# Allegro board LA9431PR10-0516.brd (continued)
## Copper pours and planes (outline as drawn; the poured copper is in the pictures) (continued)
INT_SPK_R- on TOP (solid shape): 268.87,34.04 269.1,34.04 269.41,33.73 270.18,33.73 270.23,33.68 270.23,33.48 270.19,33.44 268.85,33.44 268.29,34 268.29,34.15 268.35,34.21 268.69,34.21
INT_SPK_R- on TOP (solid shape): 273.62,22.83 273.62,22.52 273.37,22.26 273.37,21.54 273.81,21.09 273.81,20.18 273.76,20.13 272.4,20.13 272.1,20.43 272.1,22.78 272.22,22.91 273.55,22.91
INT_SPK_R- on IN1 (solid shape): 273.65,23.37 273.65,22.57 273.49,22.41 272.76,22.41 272.2,22.97 272.2,23.44 272.63,23.88 273.14,23.88
INT_SPK_R- on IN1 (solid shape): 268.83,34.04 269.32,34.04 270.12,33.24 270.12,32.93 269.63,32.45 269.44,32.45 269.01,32.88 269.01,33.22 269.01,33.23 269.01,33.32 268.26,34.06 268.26,34.16 268.36,34.26 268.61,34.26
INT_SPKR_L+ on TOP (solid shape): 281.31,19.51 281.31,15.67 280.44,14.81 279.32,14.81 279.15,14.63 279.15,13.31 279.25,13.21 283.18,13.21 283.32,13.07 283.32,12.5 283.24,12.41 281.7,12.41 281.62,12.48 278.26,12.48 277.84,12.9 277.84,15.75 279.22,17.13 279.22,19.49 279.5,19.77 281.04,19.77
INT_SPKR_L- on TOP (solid shape): 278.84,19.39 278.84,17.23 277.89,16.28 277.89,16.27 277.55,15.93 277.55,12.78 278.05,12.27 281.44,12.27 281.56,12.15 283.17,12.15 283.31,12.01 283.31,11.73 283.19,11.61 277.19,11.61 276.05,12.75 276.05,16.8 276.8,17.55 276.8,19.64 276.92,19.76 278.48,19.76
INT_SPKR_R+ on TOP (solid shape): 276.51,19.63 276.51,17.64 275.76,16.88 275.76,12.69 277.09,11.35 283.21,11.35 283.32,11.24 283.32,10.91 283.18,10.77 281.56,10.77 281.46,10.67 276,10.67 273.95,12.71 273.95,17.25 274.36,17.65 274.36,19.54 274.58,19.76 276.38,19.76
INT_SPKR_R- on TOP (solid shape): 274.08,19.57 274.08,17.75 273.57,17.25 273.57,12.66 275.82,10.41 281.61,10.41 281.71,10.52 283.2,10.52 283.3,10.41 283.3,10.03 283.01,9.74 274.46,9.74 271.93,12.27 271.93,19.64 272.09,19.8 273.85,19.8
LG_3V on TOP (solid shape): 198.22,58.83 198.22,58.34 197.76,57.89 196.47,57.89 196.27,58.09 196.27,58.58 196.63,58.95 198.09,58.95
LG_3V on TOP (solid shape): 198.32,52.43 198.32,51.26 197.76,50.7 197.76,50.41 197.71,50.35 197.57,50.35 197.51,50.41 197.51,51.16 197.7,51.34 197.7,52.41 197.79,52.5 198.25,52.5
LG_3V on IN4 (solid shape): 197.59,58.42 197.59,57.25 197.16,56.82 196.85,56.82 196.32,57.35 196.32,58.7 196.44,58.83 197.18,58.83
LG_3V on IN4 (solid shape): 198.4,53.64 198.4,51.56 198.17,51.33 197.46,51.33 197.21,51.59 197.21,53.49 197.59,53.87 198.17,53.87
LG_5V on TOP (solid shape): 193.98,61 193.98,60.17 193.85,60.05 193.03,60.05 192.84,60.24 192.84,61 192.96,61.12 193.85,61.12
LG_5V on TOP (solid shape): 196.14,51.13 196.14,50.4 196.09,50.35 195.99,50.35 195.94,50.4 195.94,50.52 195.89,50.57 195.38,50.57 194.77,51.18 194.77,51.46 194.93,51.62 195.64,51.62
LG_5V on IN4 (solid shape): 193.98,61.06 193.98,59.79 193.83,59.64 192.99,59.64 192.86,59.77 192.86,61.01 193.04,61.19 193.85,61.19
LG_5V on IN4 (solid shape): 195.31,53.99 195.31,52.26 195.78,51.79 195.78,50.75 195.63,50.6 195.38,50.6 194.32,51.65 194.32,53.96 194.5,54.14 195.16,54.14
LG_+V1.05SP on TOP (solid shape): 233.54,78.24 233.54,77.33 233.48,77.27 231.7,77.27 231.64,77.33 231.64,77.77 231.89,78.03 232.33,78.03 232.61,78.31 233.48,78.31
LG_+V1.05SP on TOP (solid shape): 236.33,76.11 236.33,75.73 236.12,75.51 236.12,75.01 236.02,74.9 235.38,74.9 235.28,75.01 235.28,75.72 235.79,76.24 236.21,76.24
LG_+V1.05SP on IN1 (solid shape): 236.33,77.02 236.33,75.96 235.74,75.36 235.26,75.36 235.13,75.49 235.13,77.09 234.96,77.25 233.16,77.25 232.49,77.93 232.49,78.27 232.82,78.6 234.76,78.6
NB_PSID on BOTTOM (solid shape): 92.62,93.08 92.62,92.66 92.36,92.4 92.28,92.34 92.22,92.26 92.02,92.06 88.95,92.06 88.84,92.18 88.84,92.43 88.88,92.47 88.88,92.49 89.67,93.29 92.41,93.29
PBATT+_C on TOP (solid shape): 172.83,9.88 172.83,5.12 171.88,4.17 171.88,2.01 171.69,1.82 167.82,1.82 167.44,2.2 167.44,5.44 168.33,6.32 168.33,9.88 168.52,10.07 172.64,10.07
REGCTL_PNP10 on TOP (solid shape): 261.06,73.06 261.06,71.93 260.97,71.84 259.52,71.84 259.49,71.86 259.49,72.93 259.78,73.21 260.91,73.21
REGCTL_PNP10 on IN1 (solid shape): outline of 145 points within 256.53,72.17 260.97,78.71
RING2 on TOP (solid shape): 277.37,39.47 277.88,39.47 278,39.34 278,38.94 277.81,38.75 275.64,38.75 274.73,37.83 274.73,36.98 274.68,36.93 274.5,36.93 274.43,36.99 274.43,38.02 275.94,39.53 276.55,39.53 276.79,39.78 277.06,39.78
RING2 on BOTTOM (solid shape): 274.66,47.65 274.66,46.63 274.49,46.46 273.84,46.46 273.47,46.82 273.47,47.6 273.57,47.7 274.61,47.7
RING2 on IN1 (solid shape): outline of 184 points within 272.96,38.73 278,47.75
RING2_L on BOTTOM (solid shape): 277.13,53.97 277.13,52.42 277.1,52.39 277.1,52.06 276.75,51.71 276.75,49.73 276.29,49.26 276.29,47.77 276,47.48 275.98,47.46 275.98,46.98 275.86,46.85 275.26,46.85 275.06,47.05 275.06,50.91 275.21,51.26 274.95,51.55 274.92,51.56 274.92,53.07 274.66,53.33 274.66,54.18 274.78,54.29 276.81,54.29
RING2_L on IN1 (solid shape): 275.92,54.11 275.92,52.37 275.5,51.96 272.87,51.96 272.69,52.13 272.69,53.81 273.13,54.24 275.79,54.24
RING2_L on IN1 (solid shape): 270.95,67.61 271.16,67.55 271.36,67.61 272.14,67.61 272.47,67.17 273,67 274.8,67 275.33,67.17 275.66,67.61 279.39,67.61 279.67,67.2 280.13,67 280.15,67 281.18,65.98 281.18,64.36 281.03,64.21 278.28,64.21 277.49,65.01 277.49,65.03 277.29,65.44 276.86,65.6 275.95,65.6 275.65,65.53 275.43,65.32 273.29,65.32 273.06,65.53 272.76,65.6 271.85,65.6 271.56,65.53 271.34,65.34 271.32,65.32 271.26,65.32 271.18,65.36 271.17,65.46 270.84,65.95 270.51,65.46 270.5,65.36 270.42,65.32 270,65.32 268.95,66.37 268.95,67.09 269.47,67.61
RUNPWROK on IN1 (solid shape): outline of 211 points within 74.16,71.41 78.98,76.75
S5_1.35V on TOP (solid shape): 119.91,11.1 119.91,8.86 119.79,8.74 119.28,8.74 118.97,9.04 118.97,9.64 118.32,10.29 116.96,10.29 116.92,10.33 116.92,10.52 116.96,10.56 118.58,10.56 119.23,11.2 119.81,11.2
SLEEVE on TOP (solid shape): 276.45,41.24 276.45,40.68 276.36,40.58 275.98,40.58 275.92,40.52 275.92,39.72 274.24,38.04 274.24,36.98 274.18,36.93 274,36.93 273.95,36.98 273.95,38.59 274.42,39.07 274.42,40.94 274.89,41.41 276.29,41.41
SLEEVE on TOP (solid shape): 271.77,51.24 271.77,50.57 271.97,50.37 272.35,50.37 272.85,49.87 272.85,48.81 272.78,48.74 271.98,48.74 270.7,50.02 270.7,51.03 271.03,51.36 271.65,51.36
SLEEVE on IN4 (solid shape): outline of 299 points within 271.28,38.68 276.02,50.43
SLEEVE_L on TOP (solid shape): 281.8,55.6 281.8,54.56 280.33,53.09 280.33,51.15 280.34,51.01 280.35,50.89 280.35,49.83 280.24,49.72 280.22,49.72 279.32,49.63 278.45,49.37 278.42,49.37 278.4,49.35 278.15,49.24 277.92,49.11 274.66,49.11 273.72,50.05 273.06,50.05 272.61,50.51 272.07,50.51 272.01,50.57 272.01,51.24 272.05,51.28 273.89,51.28 274.36,50.81 276.38,50.81 276.64,50.55 277.83,50.55 278.17,50.89 278.17,53.53 279.21,54.57 279.21,55.55 279.59,55.93 281.47,55.93
SNUB_1.35V on TOP (solid shape): 101.77,16.09 101.77,16.08 101.84,15.98 101.94,15.91 101.95,15.9 102.46,15.39 102.46,13.46 102.36,13.36 101.65,13.36 100.48,14.53 100.48,16.26 100.56,16.33 101.52,16.33
SW1 on TOP (solid shape): 192.39,61.25 192.39,58.14 192.2,57.95 191.19,57.95 190.3,57.06 187.76,57.06 187.57,57.25 187.57,61.25 187.82,61.51 192.14,61.51
SW1 on TOP (solid shape): 194.54,49.35 195.73,49.35 195.76,49.33 195.76,49.18 195.71,49.13 194.65,49.13 194.53,49.02 194.5,49.02 194.43,48.95 194.34,48.95 193.98,48.59 192.7,48.59 192.66,48.6 192.65,48.64 192.65,48.68 192.62,48.82 192.54,48.95 192.53,48.97 192.53,49.5 192.63,49.61 194.28,49.61
SW1 on BOTTOM (solid shape): 193.22,59.66 193.22,56.68 193.09,56.55 189.41,56.55 188.07,57.89 188.07,60.49 188.27,60.68 192.2,60.68
SW1 on IN4 (solid shape): 194.56,49.81 194.56,49.02 194.51,48.97 193.5,48.97 192.76,49.71 192.76,50.6 192.91,50.75 193.62,50.75
SW1 on IN4 (solid shape): 190.65,59.87 190.65,57.66 190.58,57.58 189.56,57.58 189.26,57.88 189.26,59.95 189.36,60.04 190.48,60.04
SW2 on TOP (solid shape): 202.95,61.16 202.95,56.77 202.79,56.62 201.18,56.62 201.1,56.69 201.1,58.1 200.81,58.39 198.93,58.39 198.74,58.58 198.74,60.93 199.28,61.47 202.64,61.47
SW2 on TOP (solid shape): 201.02,49.35 201.02,48.46 200.99,48.44 200.3,48.44 199.87,48.87 199.16,48.87 198.96,49.07 198.91,49.12 197.95,49.12 197.93,49.14 197.93,49.31 197.97,49.35 199.1,49.35 199.15,49.4 200.97,49.4
SW2 on BOTTOM (solid shape): 202.16,60.99 202.31,60.84 202.31,57.58 201.35,56.62 197.09,56.62 197.03,56.68 197.03,59.73 198.77,61.47 201.69,61.47
SW2 on IN1 (solid shape): 200.91,50.27 200.91,49.07 200.63,48.79 199.06,48.79 198.96,48.89 198.96,49.35 199.97,50.37 200.81,50.37
SW2 on IN1 (solid shape): 202.57,58.8 202.57,57.25 202.51,57.2 201.52,57.2 201.12,57.61 201.12,58.9 201.27,59.05 202.31,59.05
SW_1.35V on TOP (solid shape): 113.21,13.44 113.21,12.5 113.67,12.04 114.1,12.04 114.7,11.43 114.7,11.16 114.65,11.11 113.83,11.11 113.56,11.38 113.16,11.38 112.34,12.19 112.34,13.44 112.42,13.51 113.13,13.51
SW_1.35V on TOP (solid shape): 102.73,12.55 105.65,12.55 106.99,11.21 107.49,11.21 107.62,11.09 107.62,9.18 107.49,9.05 106.16,9.05 105.84,8.74 102.35,8.74 102.22,8.86 102.22,10.21 101.46,10.97 101.46,12.8 101.59,12.93 102.35,12.93
SW_1.35V on BOTTOM (solid shape): 107.85,13.54 107.85,9.25 107.34,8.74 102.44,8.74 102.26,8.91 102.26,11.53 104.8,14.07 107.32,14.07
SW_1.35V on IN4 (solid shape): 106.15,12.32 106.15,11.58 105.69,11.12 103.76,11.12 103.58,11.3 103.58,12.27 103.86,12.55 105.92,12.55
SW_1.35V on IN4 (solid shape): 113.28,12.12 114.43,12.12 114.48,12.06 114.48,11.51 114.38,11.4 111.68,11.4 111.51,11.58 111.51,12.45 111.63,12.57 112.83,12.57
SW_+V1.05SP on TOP (solid shape): 236.12,74.12 236.12,74.04 235.99,73.91 234.62,73.91 233.93,73.23 233.93,72.01 233.83,71.91 232.97,71.91 232.89,71.98 232.89,72.97 234.14,74.22 236.02,74.22
SW_+V1.05SP on TOP (solid shape): 229.67,79.48 229.67,77.88 229.79,77.75 231.11,77.75 231.24,77.62 231.24,74.6 230.91,74.27 229.87,74.27 229.87,74.27 229.58,74.27 229.44,74.12 229.44,73.46 229.31,73.33 227.51,73.33 227.38,73.46 227.38,77.01 228.77,78.4 228.77,79.54 228.83,79.6 229.54,79.6
SW_+V1.05SP on BOTTOM (solid shape): 230.56,77.7 230.68,77.7 230.88,77.49 230.88,72.83 230.82,72.77 228.18,72.77 227.29,73.66 227.29,77.48 227.51,77.7 230.56,77.7
SW_+V1.05SP on IN1 (solid shape): 228.91,77.49 228.91,74.24 228.57,73.9 227.64,73.9 227.37,74.17 227.37,77.49 227.48,77.61 228.79,77.61
SW_+V1.05SP on IN1 (solid shape): 234.49,74.12 234.49,73.76 232.84,72.11 232.26,72.11 232.11,72.26 232.11,72.85 233.55,74.29 234.32,74.29
UG_3V on TOP (solid shape): 199.39,51.28 199.39,50.47 198.81,49.89 198,49.89 197.94,49.95 197.94,50.1 198.03,50.2 198.4,50.2 198.68,50.47 198.68,51.26 198.81,51.38 199.29,51.38
UG_3V on TOP (solid shape): 200.95,57.58 200.95,56.74 200.16,55.96 199.28,55.96 199.16,56.08 199.16,56.34 199.28,56.46 199.53,56.46 199.68,56.46 199.69,56.47 199.79,56.47 200.11,56.79 200.11,56.97 200.11,56.97 200.3,57.16 200.3,57.54 200.46,57.71 200.82,57.71
UG_3V on IN1 (solid shape): 199.66,52.23 199.66,50.35 199.29,49.99 198.51,49.99 198.41,50.09 198.41,52.31 198.62,52.51 199.38,52.51
UG_3V on IN1 (solid shape): 200.66,56.49 200.66,55.07 200.38,54.79 199.18,54.79 199,54.97 199,56.49 199.1,56.59 200.56,56.59
UG_5V on TOP (solid shape): 187.38,59.47 187.38,57.25 187.25,57.12 187.06,57.12 186.74,57.44 186.74,59.47 186.8,59.54 187.31,59.54
UG_5V on TOP (solid shape): 195.25,50.27 195.61,50.27 195.73,50.14 195.73,49.95 195.7,49.91 194.65,49.91 193.73,50.84 193.73,51.22 193.85,51.35 194.17,51.35
UG_5V on IN1 (solid shape): 194.96,50.6 194.96,50.09 194.84,49.97 192.93,49.97 192.37,50.53 192.37,51.71 192.53,51.88 193.68,51.88
UG_5V on IN1 (solid shape): 187.69,59.54 187.69,58.9 188.33,58.27 188.33,57.63 188.07,57.38 187.57,57.38 186.87,58.08 186.87,59.41 187.12,59.66 187.57,59.66
UG_+V1.05SP on TOP (solid shape): 227.14,75.71 227.14,74.42 227.19,74.37 227.19,73.57 227,73.38 226.68,73.38 226.62,73.44 226.62,75.73 226.68,75.79 227.06,75.79
UG_+V1.05SP on TOP (solid shape): 236.12,73.68 236.12,73.51 236.04,73.43 235.31,73.43 234.57,72.69 234.19,72.69 234.09,72.8 234.09,73.08 234.75,73.74 236.07,73.74
UG_+V1.05SP on IN1 (solid shape): 235.19,73.57 235.19,72.3 234.57,71.68 234.19,71.68 234.09,71.78 234.09,73.02 234.82,73.76 235,73.76
UG_+V1.05SP on IN1 (solid shape): 227.13,75.67 227.13,74.44 227.18,74.39 227.18,73.84 226.93,73.58 226.55,73.58 226.36,73.77 226.36,75.53 226.56,75.73 227.07,75.73
USH_PWR_STATE# on TOP (solid shape): 191.08,8.23 191.08,6.65 190.91,6.48 190.91,5.54 190.86,5.49 190.63,5.49 190.59,5.52 190.59,6.67 189.6,7.66 189.6,8.36 190.96,8.36
N16994246 on TOP (solid shape): 54.13,14.59 54.13,12.56 54.08,12.51 53.09,12.51 52.48,13.12 51.99,13.12 51.74,13.37 51.74,13.82 51.87,13.94 52.45,13.94 53.26,14.76 53.96,14.76
N17156946 on TOP (solid shape): 52.35,41.45 52.35,40.79 52.5,40.64 53.54,40.64 53.65,40.54 53.65,37.52 53.57,37.44 53.16,37.44 52.32,38.28 51.51,38.28 51.41,38.38 51.41,39.6 51.71,39.9 51.71,40.66 51.61,40.77 51.61,41.48 51.69,41.55 52.25,41.55
N17156946 on BOTTOM (solid shape): 53.66,37.8 53.66,37.01 53.39,36.74 52.73,36.74 52.59,36.87 52.59,37.97 52.73,38.11 53.35,38.11
N17219423 on TOP (solid shape): 49.14,17.25 49.14,12.77 48.79,12.42 47.93,12.42 47.8,12.55 47.8,17.25 47.93,17.37 49.02,17.37
N17318583 on BOTTOM (solid shape): 155.68,15.26 155.68,13.94 155.6,13.87 155.04,13.87 154.69,13.51 154.69,11.3 153.77,10.39 152.6,10.39 152.48,10.52 152.48,11.33 153.92,12.78 153.92,13.74 153.64,14.02 151.84,14.02 151.46,13.64 150.34,13.64 150.09,13.89 150.09,14.99 150.5,15.39 155.55,15.39
N17321677 on TOP (solid shape): 128.07,9.42 128.07,9.25 127.69,8.86 127.69,7.72 127.88,7.53 127.88,5.88 128.19,5.56 129.34,5.56 129.59,5.31 129.59,5.12 129.53,5.05 127.88,5.05 127.58,5.35 127.58,5.36 127.57,5.36 127.43,5.5 126.86,5.5 126.73,5.63 125.4,5.63 125.03,6 125.03,6.21 125.12,6.48 124.99,6.73 124.97,6.75 124.97,6.77 124.97,8.2 125.12,8.36 125.7,8.36 125.86,8.51 125.86,8.97 126.44,9.55 127.94,9.55
N17663289 on TOP (solid shape): 69.52,12.29 69.52,5.5 69.14,5.12 65.39,5.12 64.5,4.23 64.5,3.28 64.38,3.15 63.49,3.15 63.42,3.21 63.42,9.44 65.14,11.15 65.14,13.75 65.33,13.94 67.87,13.94
N17663289 on TOP (solid shape): 52.83,12.45 52.83,11.84 52.78,11.79 52.55,11.79 52.25,11.48 52.25,10.11 52.2,10.06 52.2,9.17 52.15,9.12 51.99,9.12 51.92,9.19 51.92,10.36 51.74,10.54 51.74,12.47 51.84,12.57 52.71,12.57
N17663289 on BOTTOM (solid shape): 69.46,12.23 69.46,5.88 69.27,5.69 62.85,5.69 61.84,6.71 61.84,12.36 62.09,12.61 69.08,12.61
N17663289 on IN2 (solid shape): 52.25,12.78 52.25,10.57 52.07,10.39 51.08,10.39 50.93,10.54 50.93,12.78 51.16,13 52.02,13
N17663289 on IN2 (solid shape): 69.43,10.69 69.43,7.98 69.28,7.82 68.44,7.82 68.29,7.98 68.29,10.69 68.47,10.87 69.25,10.87
N19638084 on BOTTOM (solid shape): 100.03,98.4 100.06,98.38 100.08,98.35 100.08,97.7 100.08,97.67 100.2,97.55 101.02,97.55 101.05,97.57 101.05,98.08 101.06,98.1 101.21,98.1 101.24,98.07 101.24,97.57 101.25,97.56 102.83,97.56 103.05,97.34 103.05,96.18 103.09,96.13 103.59,96.13 103.63,96.09 103.63,95.98 103.62,95.97 103.1,95.97 103.07,95.93 103.07,95.59 103.04,95.56 102.86,95.56 102.81,95.6 102.49,95.6 102.41,95.61 102.34,95.6 100.66,95.6 99.91,94.85 99.91,92.56 99.78,92.44 97.3,92.44 97.21,92.52 97.2,92.54 97.2,92.56 97.2,95.52 97.99,96.31 98.93,97.25 98.93,98.29 99.04,98.4
N19641658 on TOP (solid shape): 41.71,7.47 42.18,7.47 42.39,7.26 42.4,7.25 42.41,7.23 42.41,6.71 42.66,6.45 43.18,6.45 43.2,6.45 43.21,6.44 43.42,6.22 43.42,6.04 43.26,5.88 42.34,5.88 41.52,6.71 41.51,6.71 41.48,6.73 41.48,6.87 40.68,6.87 40.64,6.88 40.63,6.92 40.63,7.59 40.69,7.65 41.52,7.65
N19643962 on TOP (solid shape): 43.42,4.93 43.42,4.48 43.04,4.1 43.04,3.53 42.66,3.15 41.58,3.15 41.52,3.21 41.52,4.46 42.11,5.05 43.29,5.05
N19721969 on BOTTOM (solid shape): 85.85,65.7 90.69,65.7 91.19,65.2 91.19,62.74 91.17,62.71 91.14,62.69 88.68,62.69 88.68,61.93 91.14,61.93 91.17,61.91 91.19,61.88 91.19,60.38 91.01,60.2 87.15,60.2 86.79,60.55 86.79,62.56 86.69,62.66 84.75,62.66 83.76,63.66 83.76,66.84 83.77,66.85 84.7,66.85
N19817114 on BOTTOM (solid shape): outline of 496 points within 177.06,7.04 192.66,15.44
N19817114 on IN4 (solid shape): outline of 291 points within 177.11,7.9 191.54,15.52
N19955529 on TOP (solid shape): 135.51,12.54 135.51,11.22 134.33,10.04 134.33,8.95 134.19,8.81 133.1,8.81 132.9,9.01 132.9,11.23 132.1,12.03 131.3,12.03 131.27,12.06 131.27,12.7 131.3,12.73 135.32,12.73
N19969338 on TOP (solid shape): 176.89,11.05 176.89,10.43 176.72,10.27 176.17,10.27 175.57,9.67 174.79,9.67 174.67,9.79 174.67,11.04 174.76,11.13 176.81,11.13
N20097876 on BOTTOM (solid shape): outline of 95 points within 197,6.53 200.46,10.07
N20124570 on TOP (solid shape): 94.12,89.93 94.12,88.09 93.75,87.72 93.75,87.2 93.69,87.13 93.07,87.13 93.04,87.16 93.04,87.81 93.47,88.24 93.47,89.9 93.57,90 94.04,90
N48708347 on TOP (solid shape): 111.94,13.28 111.94,11.45 111.84,11.35 111.05,11.35 110.85,11.56 110.85,13.33 110.95,13.44 111.79,13.44
N61501060 on BOTTOM (solid shape): 86.51,61.21 86.51,60.1 86.39,59.97 83.62,59.97 83.49,60.1 83.49,60.83 83.59,60.93 84.46,60.93 84.84,61.32 86.41,61.32
N66972030 on TOP (solid shape): 192,50.8 192,48.97 192,48.95 191.91,48.82 191.88,48.68 191.88,48.58 191.76,48.46 191.29,48.46 191.11,48.64 191.11,50.75 191.21,50.85 191.95,50.85
N66972333 on TOP (solid shape): 202.62,50.71 202.62,48.62 202.43,48.42 201.6,48.42 201.54,48.49 201.54,50.71 201.66,50.84 202.49,50.84
N66980103 on TOP (solid shape): 191.31,63.28 191.31,61.82 191.19,61.7 188.84,61.7 188.77,61.76 188.77,63.22 189.03,63.47 191.12,63.47
N66983215 on TOP (solid shape): 202.22,62.84 202.72,62.84 202.87,62.69 202.87,61.9 202.67,61.7 200.6,61.7 200.52,61.77 200.52,63.41 200.58,63.47 201.58,63.47
N66984844 on TOP (solid shape): 232.65,80.09 232.65,78.66 232.39,78.4 230.17,78.4 230.04,78.53 230.04,80.06 230.19,80.21 232.52,80.21
N78934544 on TOP (solid shape): 179.02,7.82 179.02,5.71 178.89,5.59 178.38,5.59 178.28,5.69 178.28,6.2 177.93,6.55 177.55,6.55 177.42,6.68 177.42,7.87 177.55,8 178.84,8
N78935279 on TOP (solid shape): 177.16,9.58 177.16,8.37 177.06,8.28 176.73,8.28 175.73,7.28 174.78,7.28 174.7,7.36 174.7,8.66 174.84,8.8 175.32,8.8 176.19,9.67 177.06,9.67
N78945927 on TOP (solid shape): 131.55,7.15 131.55,6.44 131.37,6.26 131.37,5.05 131.31,4.99 129.97,4.99 129.85,5.12 129.85,6.02 129.97,6.14 129.97,6.32 130.67,7.02 130.67,7.21 130.73,7.28 131.42,7.28
N78963697 on TOP (solid shape): 140.72,10.77 140.72,10.01 140.61,9.91 138.89,9.91 138.81,9.98 138.81,10.39 138.94,10.52 139.8,10.52 140.11,10.82 140.67,10.82
N79021833 on TOP (solid shape): 135.5,8.17 135.5,7.53 135.43,7.47 134.21,7.47 133.96,7.21 133.96,6.35 133.91,6.3 133.35,6.3 133.07,6.58 133.07,8.15 133.27,8.36 135.31,8.36
N79026826 on TOP (solid shape): 140.61,9.44 140.61,7.85 140.46,7.7 139.65,7.7 139.47,7.87 138.61,7.87 138.53,7.95 138.53,8.7 138.75,8.92 138.75,9.58 138.8,9.63 140.42,9.63
N79030038 on BOTTOM (solid shape): 205.99,4.23 206.29,4.23 206.29,4.22 206.88,4.22 207.11,3.99 207.11,3.09 206.98,2.96 204.62,2.96 203.97,3.61 203.97,4.8 204.04,4.86 205.36,4.86
N79030087 on BOTTOM (solid shape): 203.68,5.49 203.68,5.18 203.56,5.05 202.37,5.05 201.87,5.56 200.55,5.56 200.44,5.66 200.44,6.2 200.52,6.28 202.89,6.28
N79030091 on BOTTOM (solid shape): 199.24,6.26 200.04,6.26 200.2,6.1 200.2,4.63 200.07,4.5 199.53,4.5 199.39,4.64 199.39,5.34 199.12,5.6 197.72,5.6 197.31,6.02 197.31,6.53 197.61,6.83 198.67,6.83
N79030745 on BOTTOM (solid shape): 196.84,5.66 196.84,4.86 195.31,3.34 192.6,3.34 192.38,3.56 192.38,5.16 192.72,5.5 194.42,5.5 194.93,6.01 196.49,6.01
N79031357 on TOP (solid shape): 202.92,16.71 202.92,15.88 202.82,15.78 201.59,15.78 201.58,15.79 201.15,15.79 200.39,16.55 200.39,16.55 200.39,16.74 200.47,16.81 202.82,16.81
N79031406 on TOP (solid shape): 206.27,14.24 206.27,12.81 206.22,12.76 205.73,12.76 204.7,11.74 203.63,11.74 203.31,12.06 203.31,12.99 203.59,13.26 204.79,13.26 205.04,13.51 205.54,13.42 205.62,13.92 205.64,13.94 205.64,14.08 205.64,14.08 205.64,14.23 205.7,14.29 206.22,14.29
N79031414 on TOP (solid shape): 200.74,15 202.5,15 202.92,14.58 202.92,13.54 202.91,13.54 202.91,12.9 202.59,12.57 201.47,12.57 200.82,13.23 199.78,13.23 199.54,13.46 199.54,15.39 199.62,15.47 200.27,15.47
N79099120 on TOP (solid shape): 39.07,5 39.61,5 39.61,4.48 39.6,4.47 38.8,4.47 38.79,4.48 38.28,4.48 37.26,3.47 35.36,3.47 35.04,3.78 35.04,4.1 35.29,4.36 36.44,4.36 37.26,5.18 38.89,5.18
N79099501 on TOP (solid shape): 63.04,4.1 63.04,3.28 62.85,3.09 59.3,3.09 59.23,3.15 59.23,4.1 59.36,4.23 62.92,4.23
N79109047 on TOP (solid shape): 95.99,87.73 95.99,86.7 95.48,86.18 94.11,86.18 93.97,86.32 93.97,87.71 94.31,88.05 95.68,88.05
N80906026 on BOTTOM (solid shape): 96.93,93.57 96.93,92.68 96.8,92.56 96.67,92.56 96.62,92.57 96.57,92.57 95.35,92.57 95.3,92.57 95.24,92.56 94.06,92.56 93.8,92.3 93.8,91.82 93.7,91.72 93.14,91.72 92.95,91.91 92.95,93.1 93.19,93.34 94.67,93.34 95.12,93.8 96.7,93.8
N85750543 on TOP (solid shape): 234.95,71.58 234.95,70.56 234.9,70.51 232.94,70.51 232.84,70.61 232.84,71.48 232.92,71.55 234.11,71.55 234.16,71.6 234.92,71.6

Small or netless copper shapes (teardrops, artwork), in the pictures only: 24 on TOP, 297 on BOTTOM, 3 on IN1, 1 on IN2, 3 on IN3, 3 on IN4

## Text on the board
Ref Des/Silkscreen Bottom: DDR3L | LOW VOLTAGE | DIMM A | DIMM B | MB PPID
User.Comments: LA9431P | VAZ50 | kerry | 2013-03-22 | 2014-03-22 | 0.4(X02)
Ref Des/Silkscreen Top: M2x3 | 5 | 4 | 3 | 1 | 2
COMPVAL_TYPE_TOP: trace Width | Width/Space | L10BOT | L3IN1 | L4GND2 | L5IN2 | L6IN3 | L7VCC | L8IN4 | L9GND3 | L1TOP | L2GND1 | LAYER | NAME | STACKUP: 10 LAYER | SB_1_0mm (0_5oz)-10L(4mil  5mil 50ohm)-stack-up-120813 | 39 ohm | 5.2 | 50 ohm | 4 | 4.8 | 3.3 | 4.5/6.8 | 83 ohm | THICKNESS=1.0mm | 3.6/3.2 | 4/4.5 | 5.2/4.5 | 85 ohm | 3.3/3.5 | 4.8/4.9 | 90 ohm | 4/6.5 | 3.3/11.7 | 100ohm | 3.5/9 | 4/6
COMPVAL_TYPE_BOTTOM: FIGURE | SIZE | 7.0 | 8.0 | 10.0 | 20.0 | 28.0 | 35.0 | 39.0 | 47.0 | 83.0 | 91.0 | 110.0 | 134.0 | 40.0 | 43.0 | 63.0 | 71.0 | 31.0x16.0 | 39.0x28.0 | 39.0x33.0 | 59.0x24.0 | 67.0x31.0 | 69.0x28.0 | 71.0x31.0 | 79.0x31.0 | 87.0x20.0 | 87.0x31.0 | 94.0x28.0 | 102.0x28.0 | 102.0x31.0 | 110.0x39.0 | 118.0x30.0 | 55.0x43.0 | DRILL CHART: TOP to BOTTOM | ALL UNITS ARE IN MILS | PLATED | NON-PLATED | QTY | 60 | 5033 | 360 | 29 | 27 | 8 | 9 | 1 | 11 | 4 | 2 | 5 | 3 | 52 | 7
User.25: GND | +VCC_CORE | +DOCK_PWR_BAR | +5V_ALW | +1.05V_M | +PWR_SRC | +1.05V_RUN | +1.05V_MODPHY | +3.3V_ALW | +3.3V_RUN | +DC_IN
